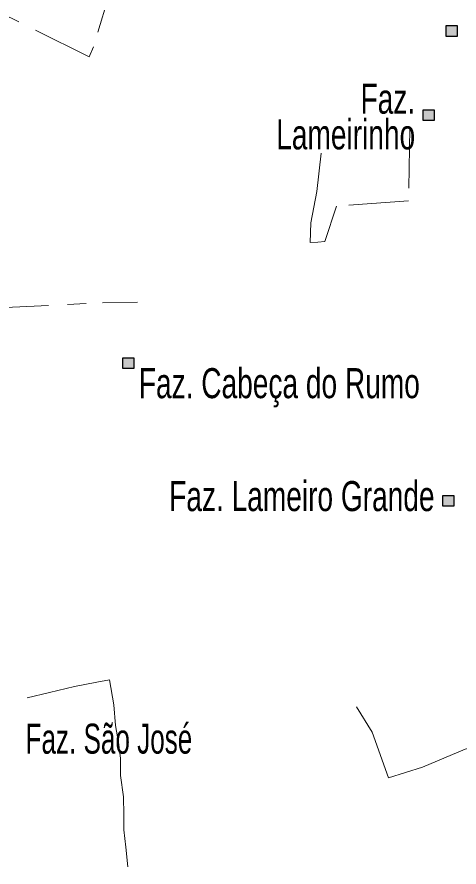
# Model space of a CAD drawing. Extents: x 445.4 to 500, y 8728.7 to 8784.
# Drawn here: x 469.667 to 472.024, y 8765.716 to 8770.246 of the extents above; entities that cross this region are included whole.
import ezdxf
from ezdxf.enums import TextEntityAlignment as Align

# ---------------------------------------------------------------- set-up
doc = ezdxf.new("R2010")
doc.units = 0
doc.header["$LTSCALE"] = 0.064
doc.linetypes.add('DOT_DASHED', pattern=[7.7, 5, -1.2, 0.3, -1.2])
doc.layers.add('2', color=7, linetype='Continuous', lineweight=25)
doc.layers.add('22', color=7, linetype='DOT_DASHED', lineweight=13)
doc.layers.add('61', color=7, linetype='Continuous')

msp = doc.modelspace()

# ---------------------------------------------------------------- hatches: boundary and pattern name
at = {"layer": '2'}
for points in [[(471.9559, 8770.2002), (472.0139, 8770.2002), (472.0139, 8770.1422), (471.9559, 8770.1422)], [(471.8337, 8769.752), (471.8917, 8769.752), (471.8917, 8769.694), (471.8337, 8769.694)], [(470.2319, 8768.43), (470.2899, 8768.43), (470.2899, 8768.372), (470.2319, 8768.372)], [(471.9378, 8767.6965), (471.9958, 8767.6965), (471.9958, 8767.6385), (471.9378, 8767.6385)]]:
    msp.add_hatch(color=256, dxfattribs=at).paths.add_polyline_path(points)

# ---------------------------------------------------------------- linework, layer by layer
for points in [[(471.9559, 8770.2002), (472.0139, 8770.2002), (472.0139, 8770.1422), (471.9559, 8770.1422)], [(471.8337, 8769.752), (471.8917, 8769.752), (471.8917, 8769.694), (471.8337, 8769.694)], [(470.2319, 8768.43), (470.2899, 8768.43), (470.2899, 8768.372), (470.2319, 8768.372)], [(471.9378, 8767.6965), (471.9958, 8767.6965), (471.9958, 8767.6385), (471.9378, 8767.6385)]]:
    msp.add_lwpolyline(points, close=True, dxfattribs=at)
at = {"layer": '22'}
for points in [[(470.3799, 8772.1367), (470.3634, 8771.2766), (470.3704, 8771.0653), (470.0742, 8770.0861), (470.0522, 8770.0328), (469.5444, 8770.2864), (469.0929, 8769.4693), (468.8954, 8769.3566), (469.2058, 8768.7438), (469.234, 8768.6944), (469.5161, 8768.6944), (470.1227, 8768.7226), (470.3102, 8768.7261)], [(471.7623, 8769.6532), (471.7548, 8769.2656), (471.3711, 8769.2385), (471.3084, 8769.0501), (471.2712, 8769.0454), (471.2305, 8769.0443), (471.2346, 8769.1496), (471.2663, 8769.3156), (471.2897, 8769.5204)], [(469.7211, 8766.618), (469.8401, 8766.6468), (469.9732, 8766.6775), (470.0919, 8766.7021), (470.1594, 8766.7144), (470.184, 8766.5812), (470.1922, 8766.4707), (470.2085, 8766.3806), (470.2188, 8766.2966), (470.2188, 8766.2045), (470.2351, 8766.0898), (470.2372, 8765.9935), (470.2372, 8765.9137), (470.2474, 8765.8215), (470.2581, 8765.7163)], [(471.4769, 8766.5703), (471.5611, 8766.4353), (471.6478, 8766.1917), (471.8284, 8766.2486), (472.0564, 8766.3435), (472.2334, 8766.3944)]]:
    msp.add_lwpolyline(points, dxfattribs=at)

# ---------------------------------------------------------------- texts
at = {"layer": '61'}
for s, width, p in [('           Faz.', 0.7, (471.7902, 8769.7306)), ('Lameirinho', 0.7, (471.7902, 8769.5406)), ('Faz. Lameiro Grande', 0.7, (471.8936, 8767.6129)), ('Faz. São José', 0.65, (470.6017, 8766.3203))]:
    msp.add_text(s, height=0.16, dxfattribs=dict(at, width=width)).set_placement(p, align=Align.RIGHT)
at = {"layer": '61', "width": 0.7}
msp.add_text('Faz. Cabeça do Rumo', height=0.16, dxfattribs=at).set_placement((470.3167, 8768.2147))

doc.saveas('drawing.dxf')
